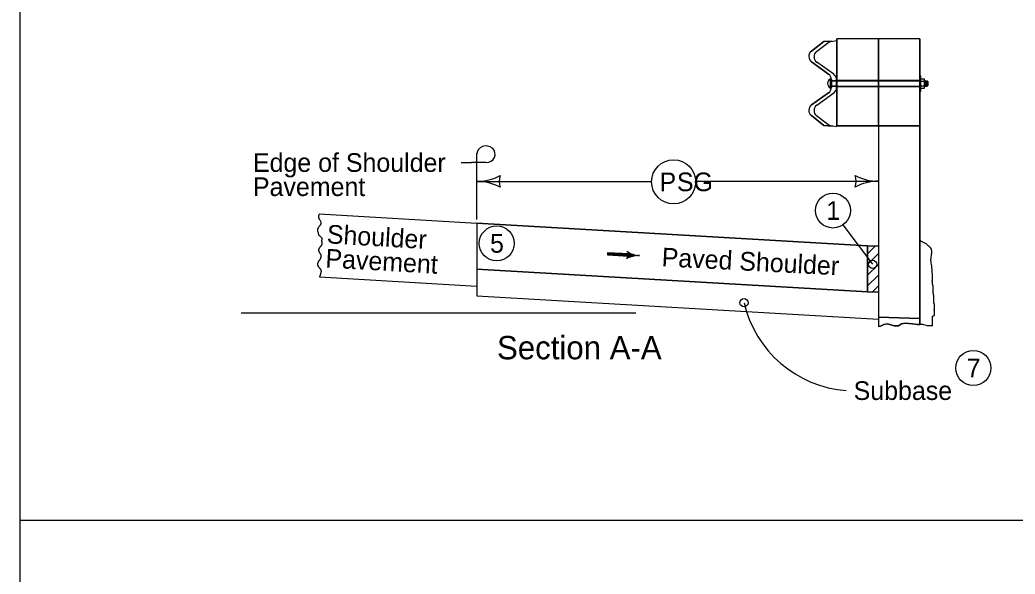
# Model space of a CAD drawing. Extents: x 6410 to 81668, y 3928 to 11667.
# Drawn here: x 6410 to 7264, y 8790 to 9265 of the extents above; entities that cross this region are included whole.
import ezdxf

# ---------------------------------------------------------------- set-up
doc = ezdxf.new("R2010")
doc.units = 0
for name, color, linetype in [('dsnNonPlotable', 7, 'Continuous'), ('dsnStdBlockModified', 7, 'Continuous'), ('dsnStdLabel', 7, 'Continuous'), ('dsnStdSection', 7, 'Continuous'), ('Level 11', 7, 'Continuous'), ('Level 14', 7, 'Continuous'), ('Level 3', 7, 'Continuous'), ('Level 7', 7, 'Continuous')]:
    doc.layers.add(name, color=color, linetype=linetype)

msp = doc.modelspace()

# ---------------------------------------------------------------- linework, layer by layer
at = {"layer": 'dsnNonPlotable'}
msp.add_line((6410.45, 9924.36), (6410.45, 8314.36), dxfattribs=at)
at = {"layer": 'dsnStdBlockModified'}
for p, q in [((7089.29, 9237.83), (7100.05, 9246.23)), ((7093.72, 9237.6), (7104.5, 9246.01)), ((7100.05, 9246.23), (7106.38, 9246.34)), ((7104.5, 9246.01), (7110.83, 9247.12)), ((7182.32, 9248.59), (7111.23, 9248.59)), ((7111.23, 9173.94), (7111.23, 9248.59)), ((7146.78, 9173.94), (7146.78, 9248.59)), ((7182.32, 9248.59), (7182.32, 9003.55)), ((7103.99, 9218.29), (7089.48, 9228.71)), ((7108.47, 9218.06), (7093.9, 9228.51)), ((7105.62, 9206.19), (7105.62, 9214.27)), ((7105.62, 9212.58), (7111.04, 9212.58)), ((7106.39, 9206.85), (7106.39, 9213.66)), ((7106.39, 9206.85), (7106.39, 9210.26)), ((7106.39, 9210.26), (7106.39, 9206.85)), ((7106.56, 9212.58), (7111.23, 9212.58)), ((7110.83, 9210.04), (7110.83, 9213.44)), ((7110.83, 9206.63), (7110.83, 9210.04)), ((7110.83, 9210.04), (7110.83, 9206.63)), ((7111.23, 9212.91), (7182.32, 9212.91)), ((7111.23, 9212.58), (7182.32, 9212.58)), ((7182.32, 9216.88), (7183, 9216.88)), ((7183, 9203.55), (7183, 9216.88)), ((7183, 9214.26), (7185.97, 9214.26)), ((7183, 9212.24), (7185.97, 9212.24)), ((7186.34, 9207.19), (7186.34, 9213.25)), ((7186.34, 9212.55), (7188.71, 9212.55)), ((7187.23, 9212.55), (7187.23, 9207.89)), ((7187.97, 9212.55), (7187.97, 9207.89)), ((7188.71, 9212.55), (7189.15, 9212.02)), ((7188.71, 9212.55), (7188.71, 9207.89)), ((7189.15, 9212.02), (7189.15, 9208.42)), ((7089.48, 9191.8), (7103.99, 9202.22)), ((7093.9, 9191.56), (7108.47, 9202.02)), ((7105.62, 9207.91), (7111.23, 9207.91)), ((7111.22, 9207.58), (7182.32, 9207.58)), ((7111.23, 9207.91), (7182.32, 9207.91)), ((7182.32, 9203.55), (7183, 9203.55)), ((7183, 9208.2), (7185.97, 9208.2)), ((7183, 9206.18), (7185.97, 9206.18)), ((7186.34, 9207.89), (7188.71, 9207.89)), ((7189.15, 9208.42), (7188.71, 9207.89)), ((7100.05, 9174.29), (7089.29, 9182.68)), ((7104.5, 9174.07), (7093.72, 9182.48)), ((7107.16, 9173.6), (7100.05, 9174.29)), ((7110.83, 9172.95), (7104.5, 9174.07)), ((7146.78, 9173.94), (7111.23, 9173.94)), ((7146.78, 9173.94), (7146.78, 9001.71)), ((6667.24, 9098.32), (6802.39, 9090.46)), ((6802.39, 9090.46), (6802.39, 9036.45)), ((6802.39, 9090.46), (7137.52, 9070.97)), ((7137.52, 9064.23), (7144.27, 9070.97)), ((7137.52, 9064.23), (7144.27, 9070.97)), ((7137.52, 9064.23), (7144.27, 9070.97)), ((7137.52, 9064.23), (7144.27, 9070.97)), ((7137.52, 9070.97), (7146.76, 9070.97)), ((7137.52, 9070.97), (7137.52, 9031.55)), ((7137.52, 9055.04), (7146.76, 9064.28)), ((7137.52, 9055.04), (7146.76, 9064.28)), ((7137.52, 9055.04), (7146.76, 9064.28)), ((7137.52, 9055.04), (7146.76, 9064.28)), ((7192.37, 9064.21), (7192.37, 9064.21)), ((7137.52, 9031.55), (6802.39, 9050.86)), ((7137.52, 9045.82), (7146.76, 9055.05)), ((7137.52, 9045.82), (7146.76, 9055.05)), ((7137.52, 9045.82), (7146.76, 9055.05)), ((7137.52, 9045.82), (7146.76, 9055.05)), ((6667.28, 9044.31), (6802.39, 9036.45)), ((7137.52, 9036.59), (7146.76, 9045.83)), ((6802.39, 9036.45), (6802.39, 9028.03)), ((7137.52, 9031.55), (7146.76, 9031.55)), ((7141.62, 9031.55), (7146.76, 9036.68)), ((6802.39, 9028.03), (7146.78, 9008.17)), ((6600.33, 9013.62), (6938.83, 9013.62))]:
    msp.add_line(p, q, dxfattribs=at)
for points in [[(7186.03, 9212.24), (7186.11, 9212.28), (7186.18, 9212.39), (7186.26, 9212.61), (7186.32, 9212.89), (7186.32, 9210.95), (7186.26, 9211.46), (7186.21, 9211.83), (7186.09, 9212.16), (7186.04, 9212.24), (7186.09, 9212.25), (7186.2, 9212.39), (7186.28, 9212.62), (7186.3, 9212.77), (7186.31, 9211.24), (7186.23, 9211.73), (7186.18, 9211.99), (7186.07, 9212.22), (7186.1, 9212.23), (7186.24, 9212.45), (7186.28, 9212.6), (7186.29, 9211.49), (7186.1, 9212.21), (7186.26, 9212.48), (7186.27, 9211.63), (7186.12, 9212.19), (7186.24, 9212.42), (7186.25, 9211.78), (7186.14, 9212.18), (7186.23, 9212.35), (7186.23, 9211.94), (7186.16, 9212.16), (7186.21, 9212.28), (7186.21, 9212.08), (7186.18, 9212.15), (7186.19, 9212.19)], [(7186.32, 9207.51), (7186.28, 9207.78), (7186.23, 9207.95), (7186.14, 9208.11), (7186.02, 9208.2), (7186.1, 9208.3), (7186.18, 9208.52), (7186.24, 9208.83), (7186.32, 9209.58), (7186.32, 9207.51), (7186.3, 9207.65), (7186.26, 9207.87), (7186.18, 9208.08), (7186.07, 9208.19), (7186.1, 9208.28), (7186.16, 9208.42), (7186.27, 9208.93), (7186.31, 9209.31), (7186.3, 9207.7), (7186.28, 9207.82), (7186.23, 9207.98), (7186.1, 9208.19), (7186.16, 9208.36), (7186.23, 9208.69), (7186.29, 9209.02), (7186.28, 9207.86), (7186.24, 9207.98), (7186.13, 9208.18), (7186.17, 9208.39), (7186.23, 9208.65), (7186.27, 9208.82), (7186.26, 9207.96), (7186.2, 9208.07), (7186.16, 9208.18), (7186.24, 9208.64), (7186.24, 9208.04), (7186.17, 9208.18), (7186.22, 9208.47), (7186.22, 9208.12), (7186.19, 9208.19), (7186.2, 9208.29), (7186.2, 9208.21)], [(7192.84, 9040.37), (7192.78, 9040.09), (7192.78, 9039.9), (7192.78, 9039.7), (7192.78, 9039.51), (7192.78, 9039.31), (7192.78, 9039.12), (7192.78, 9038.82), (7192.78, 9038.63), (7192.88, 9038.34), (7192.98, 9038.04), (7193.17, 9037.85), (7193.17, 9037.65), (7193.27, 9037.46), (7193.27, 9037.26), (7193.27, 9037.06), (7193.37, 9036.97), (7193.37, 9036.77), (7193.37, 9036.58), (7193.37, 9036.38), (7193.37, 9036.19), (7193.37, 9035.99), (7193.37, 9035.7), (7193.37, 9035.4), (7193.37, 9035.21), (7193.37, 9034.92), (7193.37, 9034.72), (7193.37, 9034.52), (7193.47, 9034.43), (7193.47, 9034.23), (7193.47, 9034.04), (7193.47, 9033.84), (7193.47, 9033.65), (7193.47, 9033.45), (7193.47, 9033.25), (7193.47, 9033.06), (7193.47, 9032.86), (7193.47, 9032.67), (7193.47, 9032.47), (7193.47, 9032.28), (7193.47, 9032.08), (7193.47, 9031.89), (7193.47, 9031.69), (7193.47, 9031.5), (7193.47, 9031.3), (7193.47, 9031.1), (7193.47, 9030.91), (7193.57, 9030.81), (7193.57, 9030.62), (7193.57, 9030.42), (7193.66, 9030.32), (7193.66, 9030.13), (7193.66, 9029.93), (7193.76, 9029.83), (7193.76, 9029.64), (7193.76, 9029.44), (7193.76, 9029.25), (7193.76, 9028.96), (7193.86, 9028.66), (7193.86, 9028.47), (7193.86, 9028.27), (7193.86, 9028.08), (7193.86, 9027.88), (7193.86, 9027.69), (7193.86, 9027.49), (7193.86, 9027.29), (7193.86, 9027.1), (7193.86, 9026.9), (7193.86, 9026.71), (7193.86, 9026.51), (7193.86, 9026.32), (7193.86, 9026.12), (7193.86, 9025.93), (7193.86, 9025.73), (7193.86, 9025.54), (7193.86, 9025.34), (7193.86, 9025.14), (7193.86, 9024.95), (7193.86, 9024.75), (7193.86, 9024.56), (7193.86, 9024.36), (7193.86, 9024.17), (7193.86, 9023.97), (7193.86, 9023.78), (7193.86, 9023.58), (7193.86, 9023.39), (7193.86, 9023.19), (7193.86, 9023), (7193.96, 9022.9), (7193.96, 9022.6), (7193.96, 9022.41), (7194.05, 9022.21), (7194.15, 9021.92), (7194.15, 9021.73), (7194.25, 9021.63), (7194.25, 9021.43), (7194.35, 9021.33), (7194.44, 9021.24), (7194.44, 9021.04), (7194.44, 9020.85), (7194.44, 9020.65), (7194.54, 9020.55), (7194.54, 9020.36), (7194.54, 9020.16), (7194.54, 9019.97), (7194.54, 9019.77), (7194.54, 9019.58), (7194.54, 9019.38), (7194.54, 9019.19), (7194.54, 9018.99), (7194.54, 9018.79), (7194.54, 9018.6), (7194.54, 9018.4), (7194.54, 9018.21), (7194.54, 9018.01), (7194.54, 9017.82), (7194.54, 9017.62), (7194.54, 9017.43), (7194.54, 9017.23), (7194.54, 9017.04), (7194.54, 9016.84), (7194.54, 9016.64), (7194.54, 9016.45), (7194.54, 9016.25), (7194.54, 9016.06), (7194.54, 9015.86), (7194.54, 9015.67), (7194.54, 9015.67), (7194.54, 9015.96), (7194.54, 9016.16), (7194.54, 9016.35), (7194.54, 9016.16), (7194.54, 9015.96), (7194.54, 9015.77), (7194.54, 9015.57), (7194.54, 9015.37), (7194.54, 9015.18), (7194.54, 9014.98), (7194.54, 9014.79), (7194.54, 9014.59), (7194.54, 9014.4), (7194.54, 9014.2), (7194.54, 9014.01), (7194.54, 9013.81), (7194.54, 9013.62), (7194.54, 9013.42), (7194.44, 9013.32), (7194.44, 9013.13), (7194.44, 9012.93), (7194.44, 9012.74), (7194.44, 9012.54), (7194.44, 9012.35), (7194.44, 9012.15), (7194.44, 9011.95), (7194.44, 9011.76), (7194.44, 9011.56), (7194.44, 9011.37), (7194.35, 9011.27), (7194.25, 9011.08), (7194.15, 9010.98), (7194.05, 9010.88), (7193.96, 9010.78), (7193.76, 9010.68), (7193.57, 9010.68), (7193.47, 9010.59), (7193.37, 9010.49), (7193.27, 9010.39), (7193.08, 9010.29), (7192.98, 9010.2), (7192.98, 9010), (7192.88, 9009.9), (7192.88, 9009.71), (7192.88, 9009.51), (7192.88, 9009.32), (7192.88, 9002.5)], [(7193.01, 9002.5), (7188.86, 9002.38), (7184.73, 9003.55), (7180.17, 9003.55), (7175.93, 9003.97), (7169.68, 9004.71), (7166.61, 9004.08), (7163.96, 9002.28), (7160.25, 9002.49), (7154.63, 9004.08), (7151.34, 9003.55), (7148.59, 9001.96), (7146.78, 9001.71)]]:
    msp.add_lwpolyline(points, dxfattribs=at)
for centre, radius, start, end in [((7092.76, 9233.34), 5.68, 127.75002, 234.69086), ((7097.21, 9233.12), 5.68, 127.75002, 234.69086), ((7100.71, 9213.66), 5.68, 360, 54.69099), ((7107.69, 9210.24), 4.54, 117.20289, 242.8461), ((7105.16, 9213.44), 5.68, 360, 54.69099), ((7100.71, 9206.85), 5.68, 305.30901, 0), ((7105.16, 9206.63), 5.68, 305.30901, 0), ((7092.76, 9187.17), 5.68, 125.30914, 232.24998), ((7097.21, 9186.95), 5.68, 125.30914, 232.24998)]:
    msp.add_arc(centre, radius, start, end, dxfattribs=at)
for centre in [(7185.97, 9213.25), (7185.97, 9207.19)]:
    msp.add_ellipse(centre, major_axis=(0, -1.01), ratio=0.362258, start_param=6.283156, end_param=9.424748, dxfattribs=at)
for points in [[(6667.24, 9098.32), (6666.74, 9094.72), (6667.78, 9093.21), (6668.65, 9090.92), (6668.04, 9088.86), (6666.13, 9086.48), (6665.62, 9084.58), (6666.13, 9082.28), (6667, 9079.91), (6668.04, 9079.2), (6669.43, 9076.66), (6669.42, 9075.82)], [(6667.45, 9058.71), (6667.67, 9058.96), (6667.86, 9059.22), (6668.22, 9059.78), (6668.5, 9060.37), (6668.61, 9060.68), (6668.71, 9060.99), (6668.85, 9061.61), (6668.89, 9062.23), (6668.85, 9062.82), (6668.79, 9063.1), (6668.75, 9063.23), (6668.71, 9063.36), (6668.5, 9063.74), (6668.21, 9064.1), (6667.92, 9064.47), (6667.67, 9064.86), (6667.53, 9065.15), (6667.39, 9065.43), (6667.13, 9066.01), (6666.93, 9066.57), (6666.85, 9066.86), (6666.8, 9067.16), (6666.79, 9067.29), (6666.79, 9067.42), (6666.94, 9068.19), (6667.15, 9068.71), (6667.41, 9069.22), (6667.85, 9069.86), (6668.37, 9070.4), (6668.88, 9070.95), (6669.11, 9071.26), (6669.31, 9071.6), (6669.52, 9072.07), (6669.67, 9072.54), (6669.78, 9073.02), (6669.81, 9073.26), (6669.82, 9073.38), (6669.83, 9073.5), (6669.79, 9074.01), (6669.63, 9074.52), (6669.58, 9074.65), (6669.53, 9074.77), (6669.48, 9074.9), (6669.46, 9075.03), (6669.42, 9075.82)], [(7192.84, 9040.37), (7193.16, 9043.27), (7192.94, 9048.14), (7192.5, 9053.89), (7191.84, 9058.31), (7192.06, 9061.62), (7192.5, 9065.83), (7191.84, 9068.92), (7189.63, 9070.91), (7187.64, 9072.68), (7185.42, 9073.79), (7183.21, 9075.11), (7182.33, 9075.78)], [(6667.45, 9058.71), (6667.24, 9058.47), (6666.99, 9058.24), (6666.76, 9058), (6666.58, 9057.73), (6666.44, 9057.45), (6666.3, 9057.16), (6666.04, 9056.59), (6665.92, 9056.31), (6665.83, 9056.02), (6665.76, 9055.73), (6665.73, 9055.58), (6665.71, 9055.43), (6665.72, 9054.92), (6665.85, 9054.4), (6666.06, 9053.88), (6666.32, 9053.37), (6666.76, 9052.74), (6667.28, 9052.19), (6667.79, 9051.64), (6668.02, 9051.34), (6668.22, 9051), (6668.62, 9050.05), (6668.73, 9049.58), (6668.74, 9049.1), (6668.71, 9048.81), (6668.66, 9048.52), (6668.6, 9048.23), (6668.54, 9047.95), (6668.22, 9046.8), (6668.04, 9046.19), (6667.85, 9045.59), (6667.62, 9045), (6667.5, 9044.71), (6667.36, 9044.42), (6667.28, 9044.31)]]:
    msp.add_spline(points, degree=3, dxfattribs=at)
at = {"layer": 'dsnStdLabel'}
msp.add_circle((6819.43, 9073.08), 15, dxfattribs=at)
at = {"layer": 'dsnStdSection'}
for p, q in [((6802.39, 9129.54), (6802.39, 9150.4)), ((6789.02, 9142.39), (6797.7, 9142.39)), ((6810.2, 9142.39), (6797.7, 9142.39)), ((6802.38, 9126.22), (6952.22, 9126.22)), ((6802.39, 9093.61), (6802.39, 9129.54)), ((6990.07, 9126.38), (7146.78, 9126.38)), ((6932.59, 9063.12), (6914.38, 9064.17)), ((6932.49, 9062.18), (6932.49, 9062.18)), ((6932.6, 9064.12), (6932.6, 9064.12))]:
    msp.add_line(p, q, dxfattribs=at)
for points in [[(6932.62, 9064.06), (6914.45, 9065.11), (6914.32, 9063.23), (6932.49, 9062.18), (6932.54, 9063.79), (6914.67, 9064.88), (6914.61, 9063.39), (6932.1, 9062.44), (6932.23, 9063.56), (6914.9, 9064.62), (6914.88, 9063.62), (6931.89, 9062.64), (6931.98, 9063.34), (6915.09, 9064.4), (6915.08, 9063.84), (6931.68, 9062.9)], [(6932.21, 9065.31), (6932.91, 9064.15), (6932.88, 9062.5), (6932.13, 9061.1), (6934.88, 9061.97), (6938.08, 9062.62), (6938.97, 9062.75), (6936.73, 9063.3), (6933.5, 9064.53), (6932.56, 9065.06), (6932.68, 9061.55), (6937.63, 9062.77), (6932.99, 9064.35), (6933, 9061.93), (6936.4, 9062.86), (6933.4, 9063.72), (6933.17, 9062.34), (6935.33, 9062.84), (6933.74, 9063.35), (6933.6, 9062.69), (6934.39, 9062.85)]]:
    msp.add_lwpolyline(points, dxfattribs=at)
msp.add_circle((6971.14, 9125.82), 18.93, dxfattribs=at)
for centre, radius, start, end in [((6802.38, 9168.72), 42.5, 270, 298.07249), ((6802.38, 9083.72), 42.5, 61.92751, 90), ((6838.02, 9126.22), 16.42, 162.26665, 197.73335), ((7111.14, 9126.38), 16.42, 342.26665, 17.73335), ((7146.78, 9168.88), 42.5, 241.92751, 270), ((7146.78, 9083.88), 42.5, 90, 118.07249), ((7126.75, 9044.3), 97.76, 193.07698, 265.55799)]:
    msp.add_arc(centre, radius, start, end, dxfattribs=at)
for centre, major_axis, start_param, end_param in [((6810.2, 9149.53), (-7.81, 0), 1.570796, 6.283185), ((6928.82, 9063.33), (3.88, 0), 5.202895, 7.237436), ((6943.88, 9082.75), (-22.17, 0), 0.954258, 1.478381), ((6941.09, 9042.33), (22.17, 0), 1.537172, 2.061295)]:
    msp.add_ellipse(centre, major_axis=major_axis, ratio=0.913811, start_param=start_param, end_param=end_param, dxfattribs=at)
at = {"layer": 'Level 11'}
for p, q in [((7141.84, 9055.15), (7116.46, 9089.07)), ((8566.03, 8835.36), (6410.45, 8835.36))]:
    msp.add_line(p, q, dxfattribs=at)
at = {"layer": 'Level 14'}
msp.add_circle((7031.52, 9022.18), 3.54, dxfattribs=at)
msp.add_circle((7031.52, 9022.18), 3.54, dxfattribs=at)
at = {"layer": 'Level 3'}
for p, q in [((7089.48, 9228.71), (7103.99, 9218.29)), ((7103.99, 9202.22), (7089.48, 9191.8)), ((7137.52, 9070.97), (6802.39, 9090.46)), ((6802.39, 9090.46), (6802.39, 9050.86)), ((7137.52, 9031.55), (7137.52, 9070.97)), ((6802.39, 9050.86), (7137.52, 9031.55))]:
    msp.add_line(p, q, dxfattribs=at)
for points in [[(7093.73, 9237.61), (7093.72, 9237.6), (7104.5, 9246.01), (7106.38, 9246.34), (7100.05, 9246.23), (7089.29, 9237.83)], [(7146.78, 9212.91), (7146.78, 9248.59), (7111.23, 9248.59), (7111.23, 9212.91), (7111.23, 9212.91), (7146.78, 9212.91)], [(7182.32, 9212.91), (7182.32, 9216.91), (7182.32, 9248.59), (7146.78, 9248.59), (7146.78, 9212.91), (7182.32, 9212.91)], [(7108.44, 9218.07), (7108.47, 9218.06), (7093.9, 9228.51), (7093.93, 9228.49)], [(7106.39, 9213.66), (7106.39, 9212.58), (7110.83, 9212.58), (7110.83, 9213.44), (7110.83, 9213.44)], [(7111.23, 9212.58), (7111.23, 9207.91), (7111.23, 9207.91), (7146.78, 9207.91), (7146.78, 9212.58), (7111.23, 9212.58), (7111.23, 9212.58)], [(7182.32, 9207.91), (7182.32, 9212.58), (7146.78, 9212.58), (7146.78, 9207.91), (7182.32, 9207.91)], [(7093.93, 9191.58), (7093.9, 9191.56), (7108.47, 9202.02), (7108.44, 9202)], [(7110.83, 9206.63), (7110.83, 9206.63), (7110.83, 9207.91), (7106.39, 9207.91), (7106.39, 9206.85), (7106.39, 9207.91), (7106.39, 9207.91), (7106.39, 9206.85)], [(7111.23, 9207.58), (7111.23, 9173.94), (7146.78, 9173.94), (7146.78, 9207.58), (7111.23, 9207.58)], [(7182.32, 9173.94), (7182.32, 9203.58), (7182.32, 9207.58), (7146.78, 9207.58), (7146.78, 9173.94), (7182.32, 9173.94)], [(7089.29, 9182.68), (7100.05, 9174.29), (7107.16, 9173.6), (7104.5, 9174.07), (7093.72, 9182.48), (7093.73, 9182.46)], [(7182.32, 9008.6), (7182.32, 9173.94), (7146.78, 9173.94), (7146.78, 9070.97), (7146.78, 9064.28), (7146.78, 9064.28), (7146.78, 9064.28), (7146.78, 9055.05), (7146.78, 9055.05), (7146.78, 9055.05), (7146.78, 9045.91), (7146.78, 9045.91), (7146.78, 9045.91), (7146.78, 9038.98), (7146.78, 9009.76), (7182.32, 9008.6)], [(7182.32, 9008.6), (7146.78, 9009.76), (7146.78, 9001.71), (7148.59, 9001.96), (7151.34, 9003.55), (7154.63, 9004.08), (7160.25, 9002.49), (7163.96, 9002.28), (7166.61, 9004.08), (7169.68, 9004.71), (7175.93, 9003.97), (7180.17, 9003.55), (7182.32, 9003.55), (7182.32, 9008.6)]]:
    msp.add_lwpolyline(points, dxfattribs=at)
msp.add_lwpolyline([(7110.83, 9212.58), (7106.39, 9212.58), (7106.39, 9209.12), (7106.39, 9210.26), (7106.39, 9207.91), (7110.83, 9207.91)], close=True, dxfattribs=at)
for centre, start, end in [((7092.76, 9233.34), 127.75002, 234.69086), ((7097.21, 9233.12), 127.75002, 234.69086), ((7100.71, 9213.66), 0, 54.69099), ((7105.16, 9213.44), 0, 54.69099), ((7100.71, 9206.85), 305.30901, 0), ((7105.16, 9206.63), 305.30901, 0), ((7092.76, 9187.17), 125.30914, 232.24998), ((7097.21, 9186.95), 125.30914, 232.24998)]:
    msp.add_arc(centre, 5.68, start, end, dxfattribs=at)
at = {"layer": 'Level 7'}
for centre, radius in [((7107.71, 9101.26), 15), ((6819.43, 9073.08), 15), ((7141.84, 9055.15), 3.58), ((7228.16, 8966.21), 15)]:
    msp.add_circle(centre, radius, dxfattribs=at)

# ---------------------------------------------------------------- texts
at = {"layer": 'dsnStdSection'}
for s, height, p in [('Edge of Shoulder ', 16, (6610.32, 9134.39)), ('P', 16, (6959.02, 9117.82)), ('SG', 16, (6973.93, 9117.82)), ('Pavement', 16, (6610.32, 9113.68)), ('Section A-A', 20, (6819.64, 8973.69)), ('Subbase', 16, (7125.53, 8938.83))]:
    msp.add_text(s, height=height, dxfattribs=at).set_placement(p)
for s, rotation, p in [('Shoulder', 356.73462, (6673.37, 9073.15)), ('Pavement', 356.73462, (6672.19, 9052.48)), ('Paved Shoulder ', 357.0678, (6960.6, 9053.48))]:
    msp.add_text(s, height=16, rotation=rotation, dxfattribs=at).set_placement(p)
at = {"layer": 'Level 7'}
for s, p in [('1', (7102.09, 9093.26)), ('5', (6813.67, 9065.08)), ('7', (7222.45, 8958.21))]:
    msp.add_text(s, height=16, dxfattribs=at).set_placement(p)

doc.saveas('drawing.dxf')
